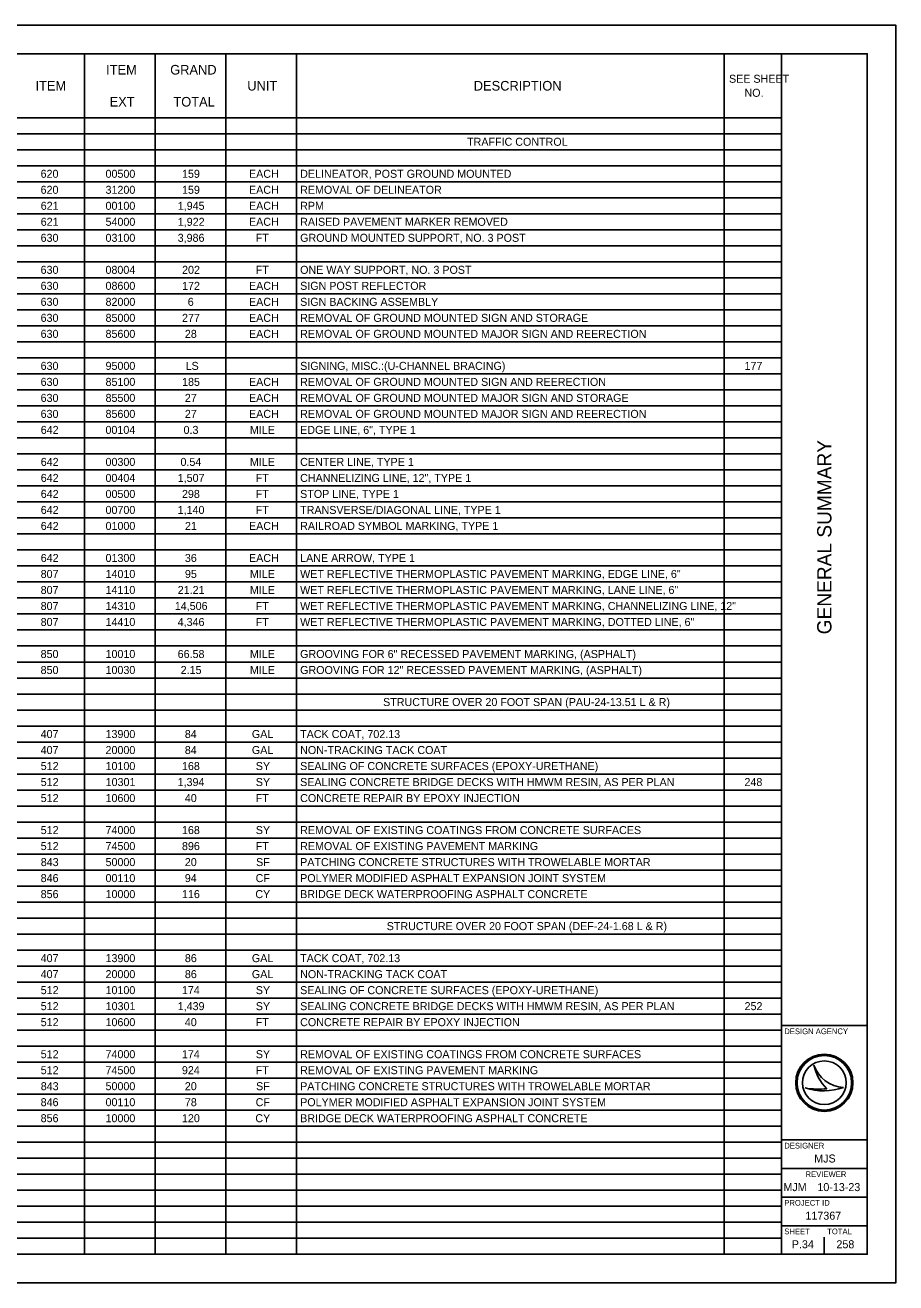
# Model space of a CAD drawing. Extents: x 0 to 34, y 0 to 22.
# Drawn here: x 18.78 to 34, y 0 to 22 of the extents above; entities that cross this region are included whole.
import ezdxf

# ---------------------------------------------------------------- set-up
doc = ezdxf.new("R2010")
doc.units = 0
for name, color, linetype in [('Default', 7, 'Continuous'), ('SH_Border', 7, 'Continuous'), ('SH_Cut_Line', 7, 'Continuous'), ('SH_Data', 7, 'Continuous')]:
    doc.layers.add(name, color=color, linetype=linetype)

msp = doc.modelspace()

# ---------------------------------------------------------------- linework, layer by layer
at = {"layer": 'Default'}
for p, q in [((1.5, 21.5), (32.004, 21.5)), ((19.815, 21.5), (19.815, 0.5)), ((21.051, 21.5), (21.051, 0.5)), ((22.286, 21.5), (22.286, 0.5)), ((23.521, 21.5), (23.521, 0.5)), ((30.999, 21.5), (30.999, 0.5)), ((32.004, 21.5), (32.004, 0.5)), ((1.5, 20.38), (32.004, 20.38)), ((1.5, 20.1), (32.004, 20.1)), ((1.5, 19.82), (32.004, 19.82)), ((1.5, 19.54), (32.004, 19.54)), ((1.5, 19.26), (32.004, 19.26)), ((1.5, 18.98), (32.004, 18.98)), ((1.5, 18.7), (32.004, 18.7)), ((1.5, 18.42), (32.004, 18.42)), ((1.5, 18.14), (32.004, 18.14)), ((1.5, 17.86), (32.004, 17.86)), ((1.5, 17.58), (32.004, 17.58)), ((1.5, 17.3), (32.004, 17.3)), ((1.5, 17.02), (32.004, 17.02)), ((1.5, 16.74), (32.004, 16.74)), ((1.5, 16.46), (32.004, 16.46)), ((1.5, 16.18), (32.004, 16.18)), ((1.5, 15.9), (32.004, 15.9)), ((1.5, 15.62), (32.004, 15.62)), ((1.5, 15.34), (32.004, 15.34)), ((1.5, 15.06), (32.004, 15.06)), ((1.5, 14.78), (32.004, 14.78)), ((1.5, 14.5), (32.004, 14.5)), ((1.5, 14.22), (32.004, 14.22)), ((1.5, 13.94), (32.004, 13.94)), ((1.5, 13.66), (32.004, 13.66)), ((1.5, 13.38), (32.004, 13.38)), ((1.5, 13.1), (32.004, 13.1)), ((1.5, 12.82), (32.004, 12.82)), ((1.5, 12.54), (32.004, 12.54)), ((1.5, 12.26), (32.004, 12.26)), ((1.5, 11.98), (32.004, 11.98)), ((1.5, 11.7), (32.004, 11.7)), ((1.5, 11.42), (32.004, 11.42)), ((1.5, 11.14), (32.004, 11.14)), ((1.5, 10.86), (32.004, 10.86)), ((1.5, 10.58), (32.004, 10.58)), ((1.5, 10.3), (32.004, 10.3)), ((1.5, 10.02), (32.004, 10.02)), ((1.5, 9.74), (32.004, 9.74)), ((1.5, 9.46), (32.004, 9.46)), ((1.5, 9.18), (32.004, 9.18)), ((1.5, 8.9), (32.004, 8.9)), ((1.5, 8.62), (32.004, 8.62)), ((1.5, 8.34), (32.004, 8.34)), ((1.5, 8.06), (32.004, 8.06)), ((1.5, 7.78), (32.004, 7.78)), ((1.5, 7.5), (32.004, 7.5)), ((1.5, 7.22), (32.004, 7.22)), ((1.5, 6.94), (32.004, 6.94)), ((1.5, 6.66), (32.004, 6.66)), ((1.5, 6.38), (32.004, 6.38)), ((1.5, 6.1), (32.004, 6.1)), ((1.5, 5.82), (32.004, 5.82)), ((1.5, 5.54), (32.004, 5.54)), ((1.5, 5.26), (32.004, 5.26)), ((1.5, 4.98), (32.004, 4.98)), ((1.5, 4.7), (32.004, 4.7)), ((1.5, 4.42), (32.004, 4.42)), ((1.5, 4.14), (32.004, 4.14)), ((1.5, 3.86), (32.004, 3.86)), ((1.5, 3.58), (32.004, 3.58)), ((1.5, 3.3), (32.004, 3.3)), ((1.5, 3.02), (32.004, 3.02)), ((1.5, 2.74), (32.004, 2.74)), ((1.5, 2.46), (32.004, 2.46)), ((1.5, 2.18), (32.004, 2.18)), ((1.5, 1.9), (32.004, 1.9)), ((1.5, 1.62), (32.004, 1.62)), ((1.5, 1.34), (32.004, 1.34)), ((1.5, 1.06), (32.004, 1.06)), ((1.5, 0.78), (32.004, 0.78)), ((1.5, 0.5), (32.004, 0.5))]:
    msp.add_line(p, q, dxfattribs=at)
at = {"layer": 'SH_Border'}
for p, q in [((32, 0.5), (32, 21.5)), ((32, 4.5), (33.5, 4.5)), ((32, 2.5), (33.5, 2.5)), ((32, 2), (33.5, 2)), ((32, 1.5), (33.5, 1.5)), ((32, 1), (33.5, 1))]:
    msp.add_line(p, q, dxfattribs=at)
msp.add_lwpolyline([(1.5, 21.5), (33.5, 21.5), (33.5, 0.5), (1.5, 0.5)], close=True, dxfattribs=at)
at = {"layer": 'SH_Cut_Line'}
msp.add_lwpolyline([(0, 0), (34, 0), (34, 22), (0, 22)], close=True, dxfattribs=at)
at = {"layer": 'SH_Data'}
for p, q in [((32.567, 3.81), (32.567, 3.81)), ((32.417, 3.41), (32.417, 3.41)), ((32.75, 3.5), (32.75, 3.5)), ((33.087, 3.419), (33.087, 3.419)), ((32.375, 0.675), (32.375, 0.675)), ((32.75, 0.5), (32.75, 0.8))]:
    msp.add_line(p, q, dxfattribs=at)
for radius in [0.5, 0.477, 0.477, 0.382]:
    msp.add_circle((32.75, 3.5), radius, dxfattribs=at)
for centre, radius, start, end in [((33.116, 3.998), 0.58, 198.9257, 198.9319), ((33.347, 3.97), 0.796, 191.6379, 191.6421), ((33.116, 3.998), 0.58, 198.9319, 267.1657), ((33.347, 3.97), 0.796, 191.6421, 226.0947), ((32.739, 4.37), 1.013, 251.4576, 290.0832), ((32.648, 4.654), 1.266, 259.4964, 259.4995), ((32.739, 4.37), 1.013, 251.4527, 251.4576), ((32.648, 4.654), 1.266, 259.4995, 276.6672)]:
    msp.add_arc(centre, radius, start, end, dxfattribs=at)

# ---------------------------------------------------------------- texts
at = {"layer": 'Default'}
for s, height, p in [('ITEM', 0.168, (20.195, 21.136)), ('GRAND', 0.168, (21.315, 21.136)), ('SEE SHEET ', 0.14, (31.084, 20.992)), ('ITEM', 0.168, (18.96, 20.856)), ('UNIT', 0.168, (22.663, 20.856)), ('DESCRIPTION', 0.168, (26.622, 20.856)), ('EXT', 0.168, (20.256, 20.576)), ('TOTAL', 0.168, (21.371, 20.576)), ('NO.', 0.14, (31.354, 20.747)), ('TRAFFIC CONTROL', 0.14, (26.505, 19.89)), ('620', 0.14, (19.05, 19.33)), ('00500', 0.14, (20.185, 19.33)), ('159', 0.14, (21.522, 19.33)), ('EACH', 0.14, (22.693, 19.33)), ('DELINEATOR, POST GROUND MOUNTED', 0.14, (23.587, 19.33)), ('620', 0.14, (19.05, 19.05)), ('31200', 0.14, (20.185, 19.05)), ('159', 0.14, (21.522, 19.05)), ('EACH', 0.14, (22.693, 19.05)), ('REMOVAL OF DELINEATOR', 0.14, (23.587, 19.05)), ('621', 0.14, (19.052, 18.77)), ('00100', 0.14, (20.185, 18.77)), ('1,945', 0.14, (21.448, 18.77)), ('EACH', 0.14, (22.693, 18.77)), ('RPM', 0.14, (23.587, 18.77)), ('621', 0.14, (19.052, 18.49)), ('54000', 0.14, (20.185, 18.49)), ('1,922', 0.14, (21.448, 18.49)), ('EACH', 0.14, (22.693, 18.49)), ('RAISED PAVEMENT MARKER REMOVED', 0.14, (23.587, 18.49)), ('630', 0.14, (19.05, 18.21)), ('03100', 0.14, (20.185, 18.21)), ('3,986', 0.14, (21.446, 18.21)), ('FT', 0.14, (22.81, 18.21)), ('GROUND MOUNTED SUPPORT, NO. 3 POST', 0.14, (23.587, 18.21)), ('630', 0.14, (19.05, 17.65)), ('08004', 0.14, (20.184, 17.65)), ('202', 0.14, (21.523, 17.65)), ('FT', 0.14, (22.81, 17.65)), ('ONE WAY SUPPORT, NO. 3 POST', 0.14, (23.587, 17.65)), ('630', 0.14, (19.05, 17.37)), ('08600', 0.14, (20.185, 17.37)), ('172', 0.14, (21.523, 17.37)), ('EACH', 0.14, (22.693, 17.37)), ('SIGN POST REFLECTOR', 0.14, (23.587, 17.37)), ('630', 0.14, (19.05, 17.09)), ('82000', 0.14, (20.185, 17.09)), ('6', 0.14, (21.622, 17.09)), ('EACH', 0.14, (22.693, 17.09)), ('SIGN BACKING ASSEMBLY', 0.14, (23.587, 17.09)), ('630', 0.14, (19.05, 16.81)), ('85000', 0.14, (20.185, 16.81)), ('277', 0.14, (21.522, 16.81)), ('EACH', 0.14, (22.693, 16.81)), ('REMOVAL OF GROUND MOUNTED SIGN AND STORAGE', 0.14, (23.587, 16.81)), ('630', 0.14, (19.05, 16.53)), ('85600', 0.14, (20.185, 16.53)), ('28', 0.14, (21.572, 16.53)), ('EACH', 0.14, (22.693, 16.53)), ('REMOVAL OF GROUND MOUNTED MAJOR SIGN AND REERECTION', 0.14, (23.587, 16.53)), ('630', 0.14, (19.05, 15.97)), ('95000', 0.14, (20.185, 15.97)), ('LS', 0.14, (21.585, 15.97)), ('SIGNING, MISC.:(U-CHANNEL BRACING)', 0.14, (23.587, 15.97)), ('177', 0.14, (31.355, 15.97)), ('630', 0.14, (19.05, 15.69)), ('85100', 0.14, (20.185, 15.69)), ('185', 0.14, (21.523, 15.69)), ('EACH', 0.14, (22.693, 15.69)), ('REMOVAL OF GROUND MOUNTED SIGN AND REERECTION', 0.14, (23.587, 15.69)), ('630', 0.14, (19.05, 15.41)), ('85500', 0.14, (20.185, 15.41)), ('27', 0.14, (21.572, 15.41)), ('EACH', 0.14, (22.693, 15.41)), ('REMOVAL OF GROUND MOUNTED MAJOR SIGN AND STORAGE', 0.14, (23.587, 15.41)), ('630', 0.14, (19.05, 15.13)), ('85600', 0.14, (20.185, 15.13)), ('27', 0.14, (21.572, 15.13)), ('EACH', 0.14, (22.693, 15.13)), ('REMOVAL OF GROUND MOUNTED MAJOR SIGN AND REERECTION', 0.14, (23.587, 15.13)), ('642', 0.14, (19.052, 14.85)), ('00104', 0.14, (20.184, 14.85)), ('0.3', 0.14, (21.549, 14.85)), ('MILE', 0.14, (22.709, 14.85)), ('EDGE LINE, 6", TYPE 1', 0.14, (23.587, 14.85)), ('642', 0.14, (19.052, 14.29)), ('00300', 0.14, (20.185, 14.29)), ('0.54', 0.14, (21.495, 14.29)), ('MILE', 0.14, (22.709, 14.29)), ('CENTER LINE, TYPE 1', 0.14, (23.587, 14.29)), ('642', 0.14, (19.052, 14.01)), ('00404', 0.14, (20.184, 14.01)), ('1,507', 0.14, (21.447, 14.01)), ('FT', 0.14, (22.81, 14.01)), ('CHANNELIZING LINE, 12", TYPE 1', 0.14, (23.587, 14.01)), ('642', 0.14, (19.052, 13.73)), ('00500', 0.14, (20.185, 13.73)), ('298', 0.14, (21.521, 13.73)), ('FT', 0.14, (22.81, 13.73)), ('STOP LINE, TYPE 1', 0.14, (23.587, 13.73)), ('642', 0.14, (19.052, 13.45)), ('00700', 0.14, (20.185, 13.45)), ('1,140', 0.14, (21.446, 13.45)), ('FT', 0.14, (22.81, 13.45)), ('TRANSVERSE/DIAGONAL LINE, TYPE 1', 0.14, (23.587, 13.45)), ('642', 0.14, (19.052, 13.17)), ('01000', 0.14, (20.185, 13.17)), ('21', 0.14, (21.573, 13.17)), ('EACH', 0.14, (22.693, 13.17)), ('RAILROAD SYMBOL MARKING, TYPE 1', 0.14, (23.587, 13.17)), ('642', 0.14, (19.052, 12.61)), ('01300', 0.14, (20.185, 12.61)), ('36', 0.14, (21.572, 12.61)), ('EACH', 0.14, (22.693, 12.61)), ('LANE ARROW, TYPE 1', 0.14, (23.587, 12.61)), ('807', 0.14, (19.051, 12.33)), ('14010', 0.14, (20.185, 12.33)), ('95', 0.14, (21.573, 12.33)), ('MILE', 0.14, (22.709, 12.33)), ('WET REFLECTIVE THERMOPLASTIC PAVEMENT MARKING, EDGE LINE, 6"', 0.14, (23.587, 12.33)), ('807', 0.14, (19.051, 12.05)), ('14110', 0.14, (20.185, 12.05)), ('21.21', 0.14, (21.447, 12.05)), ('MILE', 0.14, (22.709, 12.05)), ('WET REFLECTIVE THERMOPLASTIC PAVEMENT MARKING, LANE LINE, 6"', 0.14, (23.587, 12.05)), ('807', 0.14, (19.051, 11.77)), ('14310', 0.14, (20.185, 11.77)), ('14,506', 0.14, (21.396, 11.77)), ('FT', 0.14, (22.81, 11.77)), ('WET REFLECTIVE THERMOPLASTIC PAVEMENT MARKING, CHANNELIZING LINE, 12"', 0.14, (23.587, 11.77)), ('807', 0.14, (19.051, 11.49)), ('14410', 0.14, (20.185, 11.49)), ('4,346', 0.14, (21.446, 11.49)), ('FT', 0.14, (22.81, 11.49)), ('WET REFLECTIVE THERMOPLASTIC PAVEMENT MARKING, DOTTED LINE, 6"', 0.14, (23.587, 11.49)), ('850', 0.14, (19.05, 10.93)), ('10010', 0.14, (20.185, 10.93)), ('66.58', 0.14, (21.446, 10.93)), ('MILE', 0.14, (22.709, 10.93)), ('GROOVING FOR 6" RECESSED PAVEMENT MARKING, (ASPHALT)', 0.14, (23.587, 10.93)), ('850', 0.14, (19.05, 10.65)), ('10030', 0.14, (20.185, 10.65)), ('2.15', 0.14, (21.498, 10.65)), ('MILE', 0.14, (22.709, 10.65)), ('GROOVING FOR 12" RECESSED PAVEMENT MARKING, (ASPHALT)', 0.14, (23.587, 10.65)), ('STRUCTURE OVER 20 FOOT SPAN (PAU-24-13.51 L & R)', 0.14, (25.037, 10.09)), ('407', 0.14, (19.051, 9.53)), ('13900', 0.14, (20.185, 9.53)), ('84', 0.14, (21.571, 9.53)), ('GAL', 0.14, (22.743, 9.53)), ('TACK COAT, 702.13', 0.14, (23.587, 9.53)), ('407', 0.14, (19.051, 9.25)), ('20000', 0.14, (20.185, 9.25)), ('84', 0.14, (21.571, 9.25)), ('GAL', 0.14, (22.743, 9.25)), ('NON-TRACKING TACK COAT', 0.14, (23.587, 9.25)), ('512', 0.14, (19.052, 8.97)), ('10100', 0.14, (20.185, 8.97)), ('168', 0.14, (21.521, 8.97)), ('SY', 0.14, (22.812, 8.97)), ('SEALING OF CONCRETE SURFACES (EPOXY-URETHANE)', 0.14, (23.587, 8.97)), ('512', 0.14, (19.052, 8.69)), ('10301', 0.14, (20.187, 8.69)), ('1,394', 0.14, (21.445, 8.69)), ('SY', 0.14, (22.812, 8.69)), ('SEALING CONCRETE BRIDGE DECKS WITH HMWM RESIN, AS PER PLAN', 0.14, (23.587, 8.69)), ('248', 0.14, (31.354, 8.69)), ('512', 0.14, (19.052, 8.41)), ('10600', 0.14, (20.185, 8.41)), ('40', 0.14, (21.571, 8.41)), ('FT', 0.14, (22.81, 8.41)), ('CONCRETE REPAIR BY EPOXY INJECTION', 0.14, (23.587, 8.41)), ('512', 0.14, (19.052, 7.85)), ('74000', 0.14, (20.185, 7.85)), ('168', 0.14, (21.521, 7.85)), ('SY', 0.14, (22.812, 7.85)), ('REMOVAL OF EXISTING COATINGS FROM CONCRETE SURFACES', 0.14, (23.587, 7.85)), ('512', 0.14, (19.052, 7.57)), ('74500', 0.14, (20.185, 7.57)), ('896', 0.14, (21.521, 7.57)), ('FT', 0.14, (22.81, 7.57)), ('REMOVAL OF EXISTING PAVEMENT MARKING', 0.14, (23.587, 7.57)), ('843', 0.14, (19.053, 7.29)), ('50000', 0.14, (20.185, 7.29)), ('20', 0.14, (21.571, 7.29)), ('SF', 0.14, (22.817, 7.29)), ('PATCHING CONCRETE STRUCTURES WITH TROWELABLE MORTAR', 0.14, (23.587, 7.29)), ('846', 0.14, (19.051, 7.01)), ('00110', 0.14, (20.185, 7.01)), ('94', 0.14, (21.571, 7.01)), ('CF', 0.14, (22.809, 7.01)), ('POLYMER MODIFIED ASPHALT EXPANSION JOINT SYSTEM', 0.14, (23.587, 7.01)), ('856', 0.14, (19.051, 6.73)), ('10000', 0.14, (20.185, 6.73)), ('116', 0.14, (21.521, 6.73)), ('CY', 0.14, (22.804, 6.73)), ('BRIDGE DECK WATERPROOFING ASPHALT CONCRETE', 0.14, (23.587, 6.73)), ('STRUCTURE OVER 20 FOOT SPAN (DEF-24-1.68 L & R)', 0.14, (25.1, 6.17)), ('407', 0.14, (19.051, 5.61)), ('13900', 0.14, (20.185, 5.61)), ('86', 0.14, (21.572, 5.61)), ('GAL', 0.14, (22.743, 5.61)), ('TACK COAT, 702.13', 0.14, (23.587, 5.61)), ('407', 0.14, (19.051, 5.33)), ('20000', 0.14, (20.185, 5.33)), ('86', 0.14, (21.572, 5.33)), ('GAL', 0.14, (22.743, 5.33)), ('NON-TRACKING TACK COAT', 0.14, (23.587, 5.33)), ('512', 0.14, (19.052, 5.05)), ('10100', 0.14, (20.185, 5.05)), ('174', 0.14, (21.52, 5.05)), ('SY', 0.14, (22.812, 5.05)), ('SEALING OF CONCRETE SURFACES (EPOXY-URETHANE)', 0.14, (23.587, 5.05)), ('512', 0.14, (19.052, 4.77)), ('10301', 0.14, (20.187, 4.77)), ('1,439', 0.14, (21.447, 4.77)), ('SY', 0.14, (22.812, 4.77)), ('SEALING CONCRETE BRIDGE DECKS WITH HMWM RESIN, AS PER PLAN', 0.14, (23.587, 4.77)), ('252', 0.14, (31.356, 4.77)), ('512', 0.14, (19.052, 4.49)), ('10600', 0.14, (20.185, 4.49)), ('40', 0.14, (21.571, 4.49)), ('FT', 0.14, (22.81, 4.49)), ('CONCRETE REPAIR BY EPOXY INJECTION', 0.14, (23.587, 4.49)), ('512', 0.14, (19.052, 3.93)), ('74000', 0.14, (20.185, 3.93)), ('174', 0.14, (21.52, 3.93)), ('SY', 0.14, (22.812, 3.93)), ('REMOVAL OF EXISTING COATINGS FROM CONCRETE SURFACES', 0.14, (23.587, 3.93)), ('512', 0.14, (19.052, 3.65)), ('74500', 0.14, (20.185, 3.65)), ('924', 0.14, (21.52, 3.65)), ('FT', 0.14, (22.81, 3.65)), ('REMOVAL OF EXISTING PAVEMENT MARKING', 0.14, (23.587, 3.65)), ('843', 0.14, (19.053, 3.37)), ('50000', 0.14, (20.185, 3.37)), ('20', 0.14, (21.571, 3.37)), ('SF', 0.14, (22.817, 3.37)), ('PATCHING CONCRETE STRUCTURES WITH TROWELABLE MORTAR', 0.14, (23.587, 3.37)), ('846', 0.14, (19.051, 3.09)), ('00110', 0.14, (20.185, 3.09)), ('78', 0.14, (21.572, 3.09)), ('CF', 0.14, (22.809, 3.09)), ('POLYMER MODIFIED ASPHALT EXPANSION JOINT SYSTEM', 0.14, (23.587, 3.09)), ('856', 0.14, (19.051, 2.81)), ('10000', 0.14, (20.185, 2.81)), ('120', 0.14, (21.521, 2.81)), ('CY', 0.14, (22.804, 2.81)), ('BRIDGE DECK WATERPROOFING ASPHALT CONCRETE', 0.14, (23.587, 2.81))]:
    msp.add_text(s, height=height, dxfattribs=at).set_placement(p)
at = {"layer": 'SH_Data'}
msp.add_text('GENERAL SUMMARY', height=0.25, rotation=90, dxfattribs=at).set_placement((32.875, 11.344))
for s, height, p in [('DESIGN AGENCY', 0.1, (32.05, 4.35)), ('DESIGNER', 0.1, (32.05, 2.35)), ('MJS', 0.14, (32.574, 2.105)), ('REVIEWER', 0.1, (32.422, 1.85)), ('MJM', 0.14, (32.035, 1.605)), ('10-13-23', 0.14, (32.629, 1.605)), ('PROJECT ID', 0.1, (32.05, 1.35)), ('117367', 0.14, (32.42, 1.105)), ('SHEET', 0.1, (32.05, 0.85)), ('TOTAL', 0.1, (32.8, 0.85)), ('P.34', 0.14, (32.182, 0.605)), ('258', 0.14, (32.962, 0.605))]:
    msp.add_text(s, height=height, dxfattribs=at).set_placement(p)

doc.saveas('drawing.dxf')
